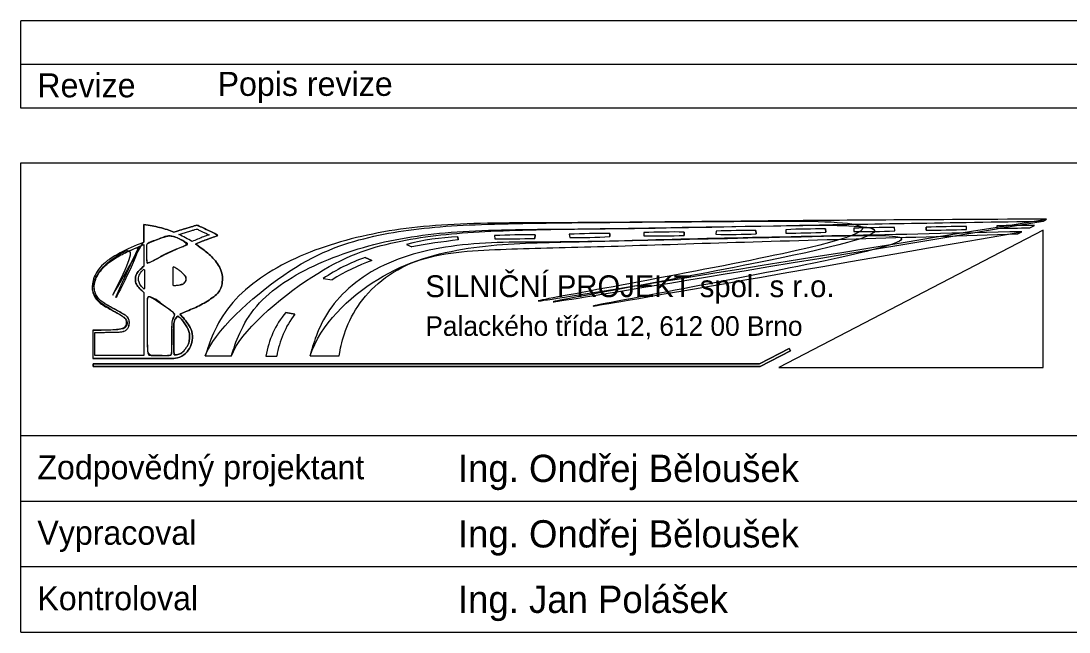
# Model space of a CAD drawing. Extents: x -598463 to -598043, y -1203644 to -1203347.
# Drawn here: x -598223.2 to -598127.3, y -1203502.3 to -1203446.3 of the extents above; entities that cross this region are included whole.
import ezdxf

# ---------------------------------------------------------------- set-up
doc = ezdxf.new("R2010")
doc.units = 0
doc.layers.add('AQP_ROZPISKA', color=7, linetype='Continuous')

msp = doc.modelspace()

# ---------------------------------------------------------------- linework, layer by layer
at = {"layer": 'AQP_ROZPISKA'}
for p, q in [((-598053.212, -1203446.256), (-598223.212, -1203446.256)), ((-598223.212, -1203454.256), (-598223.212, -1203446.256)), ((-598053.212, -1203450.256), (-598223.212, -1203450.256)), ((-598053.212, -1203454.256), (-598223.212, -1203454.256)), ((-598129.633, -1203464.599), (-598129.332, -1203464.413)), ((-598129.633, -1203464.599), (-598129.332, -1203464.413)), ((-598211.962, -1203466.533), (-598211.959, -1203464.908)), ((-598211.959, -1203464.908), (-598211.962, -1203466.533)), ((-598159.57, -1203465.508), (-598159.593, -1203465.806)), ((-598159.57, -1203465.508), (-598159.593, -1203465.806)), ((-598155.933, -1203465.451), (-598155.913, -1203465.767)), ((-598155.913, -1203465.767), (-598155.933, -1203465.451)), ((-598129.655, -1203465.429), (-598153.831, -1203478.006)), ((-598129.655, -1203465.429), (-598153.831, -1203478.006)), ((-598153.186, -1203465.385), (-598153.183, -1203465.7)), ((-598153.186, -1203465.385), (-598153.183, -1203465.7)), ((-598149.577, -1203465.318), (-598149.522, -1203465.625)), ((-598149.522, -1203465.625), (-598149.577, -1203465.318)), ((-598146.97, -1203465.253), (-598146.964, -1203465.544)), ((-598146.97, -1203465.253), (-598146.964, -1203465.544)), ((-598143.228, -1203465.495), (-598143.241, -1203465.178)), ((-598143.228, -1203465.495), (-598143.241, -1203465.178)), ((-598140.34, -1203465.428), (-598140.358, -1203465.169)), ((-598140.358, -1203465.169), (-598140.34, -1203465.428)), ((-598136.674, -1203465.369), (-598136.673, -1203465.099)), ((-598136.674, -1203465.369), (-598136.673, -1203465.099)), ((-598133.888, -1203465.03), (-598133.898, -1203465.262)), ((-598133.888, -1203465.03), (-598133.898, -1203465.262)), ((-598130.866, -1203465.203), (-598130.448, -1203465.011)), ((-598130.866, -1203465.203), (-598130.448, -1203465.011)), ((-598129.655, -1203478.006), (-598129.655, -1203465.429)), ((-598129.655, -1203478.006), (-598129.655, -1203465.429)), ((-598183.211, -1203466.041), (-598183.179, -1203466.326)), ((-598183.179, -1203466.326), (-598183.211, -1203466.041)), ((-598179.853, -1203465.93), (-598179.838, -1203466.21)), ((-598179.853, -1203465.93), (-598179.838, -1203466.21)), ((-598176.149, -1203465.867), (-598176.177, -1203466.19)), ((-598176.177, -1203466.19), (-598176.149, -1203465.867)), ((-598173.029, -1203465.808), (-598172.977, -1203466.094)), ((-598173.029, -1203465.808), (-598172.977, -1203466.094)), ((-598169.299, -1203465.727), (-598169.294, -1203466.016)), ((-598169.294, -1203466.016), (-598169.299, -1203465.727)), ((-598166.189, -1203465.658), (-598166.196, -1203465.937)), ((-598166.189, -1203465.658), (-598166.196, -1203465.937)), ((-598162.495, -1203465.605), (-598162.513, -1203465.913)), ((-598162.513, -1203465.913), (-598162.495, -1203465.605)), ((-598131.972, -1203465.766), (-598131.604, -1203465.567)), ((-598131.972, -1203465.766), (-598131.604, -1203465.567)), ((-598211.963, -1203466.747), (-598211.963, -1203468.727)), ((-598211.963, -1203466.747), (-598211.963, -1203468.727)), ((-598187.929, -1203466.73), (-598187.444, -1203466.945)), ((-598187.929, -1203466.73), (-598187.444, -1203466.945)), ((-598191.699, -1203467.945), (-598191.104, -1203468.212)), ((-598191.104, -1203468.212), (-598191.699, -1203467.945)), ((-598195.545, -1203469.872), (-598194.732, -1203469.978)), ((-598195.545, -1203469.872), (-598194.732, -1203469.978)), ((-598211.963, -1203471.129), (-598211.963, -1203476.903)), ((-598211.963, -1203471.129), (-598211.963, -1203476.903)), ((-598198.975, -1203472.968), (-598198.156, -1203473.126)), ((-598198.156, -1203473.126), (-598198.975, -1203472.968)), ((-598216.635, -1203474.595), (-598216.635, -1203477.181)), ((-598216.635, -1203474.595), (-598216.635, -1203477.181)), ((-598216.458, -1203476.903), (-598216.458, -1203474.799)), ((-598216.458, -1203476.903), (-598216.458, -1203474.799)), ((-598211.963, -1203476.903), (-598216.458, -1203476.903)), ((-598211.963, -1203476.903), (-598216.458, -1203476.903)), ((-598206.34, -1203476.951), (-598203.942, -1203476.951)), ((-598206.34, -1203476.951), (-598203.942, -1203476.951)), ((-598200.784, -1203476.966), (-598199.796, -1203476.966)), ((-598200.784, -1203476.966), (-598199.796, -1203476.966)), ((-598196.752, -1203476.951), (-598194.095, -1203476.951)), ((-598196.752, -1203476.951), (-598194.095, -1203476.951)), ((-598155.62, -1203477.69), (-598152.888, -1203476.278)), ((-598152.888, -1203476.278), (-598155.62, -1203477.69)), ((-598152.78, -1203476.493), (-598155.549, -1203477.932)), ((-598155.549, -1203477.932), (-598152.78, -1203476.493)), ((-598152.888, -1203476.278), (-598152.78, -1203476.493)), ((-598152.78, -1203476.493), (-598152.888, -1203476.278)), ((-598209.725, -1203477.181), (-598216.635, -1203477.181)), ((-598216.635, -1203477.181), (-598210.267, -1203477.181)), ((-598216.607, -1203477.69), (-598155.62, -1203477.69)), ((-598216.607, -1203477.932), (-598216.607, -1203477.69)), ((-598216.607, -1203477.69), (-598216.607, -1203477.932)), ((-598155.62, -1203477.69), (-598216.607, -1203477.69)), ((-598155.549, -1203477.932), (-598216.607, -1203477.932)), ((-598216.607, -1203477.932), (-598155.549, -1203477.932)), ((-598153.831, -1203478.006), (-598129.655, -1203478.006)), ((-598153.831, -1203478.006), (-598129.655, -1203478.006)), ((-598223.212, -1203484.256), (-598053.212, -1203484.256)), ((-598223.212, -1203502.256), (-598223.212, -1203484.256)), ((-598223.212, -1203490.256), (-598053.212, -1203490.256)), ((-598223.212, -1203496.256), (-598053.212, -1203496.256)), ((-598223.212, -1203502.256), (-598053.212, -1203502.256))]:
    msp.add_line(p, q, dxfattribs=at)
msp.add_lwpolyline([(-598223.212, -1203484.256), (-598223.212, -1203459.256), (-598053.212, -1203459.256), (-598053.212, -1203484.256)], dxfattribs=at)
for centre, radius, start, end in [((-598155.311, -1203620.625), 155.175, 90.22938, 91.57245), ((-598155.311, -1203620.625), 155.175, 90.22938, 91.57245), ((-598149.992, -1203540.263), 74.946, 89.68255, 92.44261), ((-598149.992, -1203540.263), 74.946, 89.68255, 92.44261), ((-598142.721, -1203583.61), 118.433, 90.25153, 92.05616), ((-598142.721, -1203583.61), 118.433, 90.25153, 92.05616), ((-598146.074, -1203390.971), 74.579, 269.31629, 272.1867), ((-598146.074, -1203390.971), 74.579, 269.31629, 272.1867), ((-598136.968, -1203546.2), 81.102, 89.79178, 92.39563), ((-598136.968, -1203546.2), 81.102, 89.79178, 92.39563), ((-598141.154, -1203301.248), 164.182, 270.28419, 271.56359), ((-598141.154, -1203301.248), 164.182, 270.28419, 271.56359), ((-598134.121, -1203376.193), 89.069, 270.14354, 272.0944), ((-598134.121, -1203376.193), 89.069, 270.14354, 272.0944), ((-598131.795, -1203533), 68.002, 88.8652, 91.76433), ((-598131.795, -1203533), 68.002, 88.8652, 91.76433), ((-598212.66, -1203474.288), 9.329, 56.87051, 65.23041), ((-598212.66, -1203474.288), 9.329, 56.87051, 65.23041), ((-598182.285, -1203488.869), 22.847, 92.32313, 104.30365), ((-598182.285, -1203488.869), 22.847, 92.32313, 104.30365), ((-598175.607, -1203533.524), 67.623, 96.42923, 100.08156), ((-598175.607, -1203533.524), 67.623, 96.42923, 100.08156), ((-598176.927, -1203529.113), 63.251, 89.29557, 92.65207), ((-598176.927, -1203529.113), 63.251, 89.29557, 92.65207), ((-598178.77, -1203328.379), 137.835, 269.55627, 271.07803), ((-598178.77, -1203328.379), 137.835, 269.55627, 271.07803), ((-598169.502, -1203542.005), 76.278, 89.8478, 92.64998), ((-598169.502, -1203542.005), 76.278, 89.8478, 92.64998), ((-598172.228, -1203414.553), 51.547, 269.16831, 273.26307), ((-598172.228, -1203414.553), 51.547, 269.16831, 273.26307), ((-598164.885, -1203384.363), 81.585, 269.07935, 271.66629), ((-598164.885, -1203384.363), 81.585, 269.07935, 271.66629), ((-598163.514, -1203523.87), 58.274, 88.99776, 92.63098), ((-598163.514, -1203523.87), 58.274, 88.99776, 92.63098), ((-598158.488, -1203397.225), 68.591, 269.07696, 272.15166), ((-598158.488, -1203397.225), 68.591, 269.07696, 272.15166), ((-598154.109, -1203331.069), 134.635, 270.39407, 271.95283), ((-598154.109, -1203331.069), 134.635, 270.39407, 271.95283), ((-598186.881, -1203482.359), 15.199, 108.48338, 124.75427), ((-598186.881, -1203482.359), 15.199, 108.48338, 124.75427), ((-598184.984, -1203485.4), 18.245, 109.60015, 122.29398), ((-598184.984, -1203485.4), 18.245, 109.60015, 122.29398), ((-598192.602, -1203478.26), 8.284, 140.29298, 171.00995), ((-598192.602, -1203478.26), 8.284, 140.29298, 171.00995), ((-598190.881, -1203478.504), 9.047, 143.53116, 170.21409), ((-598190.881, -1203478.504), 9.047, 143.53116, 170.21409)]:
    msp.add_arc(centre, radius, start, end, dxfattribs=at)
for points, degree in [([(-598206.34, -1203476.951), (-598205.581, -1203474.773), (-598198.645, -1203468.365), (-598191.35, -1203465.827), (-598184.203, -1203464.916), (-598174.634, -1203464.75), (-598158.871, -1203464.629), (-598129.332, -1203464.413), (-598206.34, -1203476.951), (-598129.332, -1203464.413)], 3), ([(-598129.332, -1203464.413), (-598139.178, -1203464.47), (-598154.278, -1203464.557), (-598172.572, -1203464.791), (-598183.411, -1203464.704), (-598191.59, -1203465.617), (-598199.259, -1203468.134), (-598204.978, -1203472.435), (-598206.117, -1203476.21), (-598206.34, -1203476.951)], 3), ([(-598211.959, -1203464.908), (-598211.441, -1203464.992), (-598210.507, -1203465.143), (-598209.61, -1203465.452), (-598209.219, -1203465.616)], 3), ([(-598209.219, -1203465.616), (-598209.61, -1203465.452), (-598210.507, -1203465.143), (-598211.441, -1203464.992), (-598211.959, -1203464.908)], 3), ([(-598209.219, -1203465.616), (-598208.634, -1203465.424), (-598207.977, -1203465.213), (-598207.272, -1203465.023), (-598207.114, -1203464.967), (-598206.985, -1203465.009), (-598206.836, -1203465.089), (-598206.278, -1203465.354), (-598205.664, -1203465.621), (-598205.251, -1203465.858), (-598205.17, -1203465.902), (-598205.24, -1203465.955), (-598205.422, -1203466.009), (-598206.117, -1203466.246), (-598206.753, -1203466.497), (-598207.231, -1203466.701)], 3), ([(-598207.231, -1203466.701), (-598206.753, -1203466.497), (-598206.117, -1203466.246), (-598205.422, -1203466.009), (-598205.24, -1203465.955), (-598205.17, -1203465.902), (-598205.251, -1203465.858), (-598205.664, -1203465.621), (-598206.278, -1203465.354), (-598206.836, -1203465.089), (-598206.985, -1203465.009), (-598207.114, -1203464.967), (-598207.272, -1203465.023), (-598207.977, -1203465.213), (-598208.634, -1203465.424), (-598209.219, -1203465.616)], 3), ([(-598208.751, -1203465.817), (-598208.615, -1203465.773), (-598208.35, -1203465.688), (-598207.957, -1203465.567), (-598207.568, -1203465.451), (-598207.285, -1203465.377), (-598207.134, -1203465.33), (-598207.114, -1203465.323)], 3), ([(-598208.751, -1203465.817), (-598208.615, -1203465.773), (-598208.35, -1203465.688), (-598207.957, -1203465.567), (-598207.568, -1203465.451), (-598207.285, -1203465.377), (-598207.134, -1203465.33), (-598207.114, -1203465.323)], 3), ([(-598207.114, -1203465.323), (-598207.089, -1203465.333), (-598207.003, -1203465.383), (-598206.85, -1203465.455), (-598206.595, -1203465.574), (-598206.308, -1203465.704), (-598206.088, -1203465.81), (-598205.993, -1203465.854)], 3), ([(-598207.114, -1203465.323), (-598207.089, -1203465.333), (-598207.003, -1203465.383), (-598206.85, -1203465.455), (-598206.595, -1203465.574), (-598206.308, -1203465.704), (-598206.088, -1203465.81), (-598205.993, -1203465.854)], 3), ([(-598203.942, -1203476.951), (-598203.183, -1203474.773), (-598195.966, -1203468.563), (-598188.945, -1203466.276), (-598181.659, -1203465.471), (-598172.074, -1203465.319), (-598156.079, -1203465.065), (-598129.633, -1203464.599), (-598203.942, -1203476.951), (-598129.633, -1203464.599)], 3), ([(-598203.942, -1203476.951), (-598203.721, -1203476.208), (-598202.586, -1203472.396), (-598196.655, -1203468.43), (-598189.039, -1203466.022), (-598180.895, -1203465.306), (-598169.943, -1203465.363), (-598152.592, -1203464.975), (-598138.447, -1203464.743), (-598129.633, -1203464.599)], 3), ([(-598211.712, -1203466.789), (-598211.708, -1203466.757), (-598211.699, -1203466.691), (-598211.304, -1203466.453), (-598210.636, -1203466.29), (-598209.837, -1203465.882), (-598209.227, -1203465.99), (-598208.802, -1203466.203), (-598208.458, -1203466.353), (-598207.783, -1203466.7), (-598208.166, -1203466.821), (-598208.745, -1203467.067), (-598209.993, -1203467.544), (-598210.829, -1203468.106), (-598211.705, -1203468.529), (-598211.702, -1203468.207), (-598211.723, -1203467.714), (-598211.717, -1203467.193), (-598211.712, -1203466.789)], 3), ([(-598211.712, -1203466.789), (-598211.687, -1203466.7), (-598211.612, -1203466.64), (-598210.58, -1203466.226), (-598209.687, -1203465.947), (-598209.192, -1203466.025), (-598208.85, -1203466.176), (-598208.403, -1203466.386), (-598207.982, -1203466.732), (-598208.191, -1203466.834), (-598208.308, -1203466.881), (-598209.8, -1203467.519), (-598211.517, -1203468.437), (-598211.664, -1203468.477), (-598211.704, -1203468.288), (-598211.712, -1203467.948), (-598211.712, -1203466.789), (-598211.712, -1203466.789), (-598211.712, -1203466.789)], 3), ([(-598205.993, -1203465.854), (-598206.061, -1203465.879), (-598206.263, -1203465.949), (-598206.591, -1203466.076), (-598207.046, -1203466.256), (-598207.368, -1203466.393), (-598207.561, -1203466.475)], 3), ([(-598205.993, -1203465.854), (-598206.061, -1203465.879), (-598206.263, -1203465.949), (-598206.591, -1203466.076), (-598207.046, -1203466.256), (-598207.368, -1203466.393), (-598207.561, -1203466.475)], 3), ([(-598196.752, -1203476.951), (-598195.802, -1203474.094), (-598190.679, -1203469.079), (-598182.256, -1203466.732), (-598173.938, -1203466.523), (-598164.677, -1203466.317), (-598149.021, -1203465.963), (-598131.604, -1203465.567), (-598196.752, -1203476.951), (-598131.604, -1203465.567)], 3), ([(-598131.604, -1203465.567), (-598137.41, -1203465.705), (-598148.434, -1203465.965), (-598162.547, -1203466.225), (-598173.621, -1203466.606), (-598182.407, -1203466.4), (-598190.436, -1203468.176), (-598195.606, -1203472.665), (-598196.491, -1203475.972), (-598196.752, -1203476.951)], 3), ([(-598194.095, -1203476.951), (-598193.963, -1203476.214), (-598193.326, -1203472.678), (-598187.972, -1203467.737), (-598179.884, -1203467.13), (-598171.459, -1203466.998), (-598160.532, -1203466.604), (-598147.065, -1203466.238), (-598136.909, -1203465.921), (-598131.972, -1203465.766)], 3), ([(-598194.095, -1203476.951), (-598193.963, -1203476.214), (-598193.326, -1203472.678), (-598187.972, -1203467.737), (-598179.884, -1203467.13), (-598171.459, -1203466.998), (-598160.532, -1203466.604), (-598147.065, -1203466.238), (-598136.909, -1203465.921), (-598131.972, -1203465.766)], 3), ([(-598212.041, -1203466.559), (-598212.773, -1203466.864), (-598214.203, -1203467.46), (-598216.006, -1203468.662), (-598216.75, -1203470.1), (-598216.684, -1203471.177), (-598216.275, -1203471.956), (-598215.174, -1203472.626), (-598214.27, -1203473.081), (-598213.519, -1203473.556), (-598213.455, -1203473.994), (-598213.673, -1203474.538), (-598214.967, -1203474.589), (-598215.917, -1203474.593), (-598216.635, -1203474.595)], 3), ([(-598216.635, -1203474.595), (-598214.376, -1203474.564), (-598213.667, -1203474.382), (-598213.497, -1203473.999), (-598213.586, -1203473.561), (-598213.846, -1203473.351), (-598215.393, -1203472.481), (-598216.222, -1203471.877), (-598216.672, -1203471.005), (-598216.705, -1203470.527), (-598216.005, -1203468.93), (-598214.206, -1203467.547), (-598212.041, -1203466.559), (-598216.635, -1203474.595), (-598212.041, -1203466.559)], 3), ([(-598216.458, -1203474.799), (-598216.219, -1203474.798), (-598215.826, -1203474.795), (-598215.275, -1203474.789), (-598214.795, -1203474.779), (-598214.379, -1203474.77), (-598214.074, -1203474.754), (-598213.891, -1203474.722), (-598213.752, -1203474.679), (-598213.616, -1203474.609), (-598213.496, -1203474.507), (-598213.404, -1203474.377), (-598213.341, -1203474.235), (-598213.301, -1203474.086), (-598213.284, -1203473.933), (-598213.29, -1203473.777), (-598213.324, -1203473.621), (-598213.392, -1203473.473), (-598213.494, -1203473.351), (-598213.61, -1203473.259), (-598213.823, -1203473.124), (-598214.266, -1203472.866), (-598214.813, -1203472.572), (-598215.282, -1203472.312), (-598215.542, -1203472.159), (-598215.728, -1203472.038), (-598215.9, -1203471.908), (-598216.055, -1203471.764), (-598216.189, -1203471.604), (-598216.303, -1203471.427), (-598216.394, -1203471.238), (-598216.46, -1203471.041), (-598216.498, -1203470.837), (-598216.509, -1203470.63), (-598216.495, -1203470.421), (-598216.457, -1203470.213), (-598216.398, -1203470.008), (-598216.319, -1203469.805), (-598216.221, -1203469.607), (-598216.108, -1203469.414), (-598215.982, -1203469.228), (-598215.843, -1203469.051), (-598215.695, -1203468.882), (-598215.539, -1203468.723), (-598215.374, -1203468.571), (-598215.145, -1203468.38), (-598214.841, -1203468.158), (-598214.457, -1203467.917), (-598214.058, -1203467.696), (-598213.65, -1203467.488), (-598213.235, -1203467.292), (-598212.673, -1203467.043), (-598212.247, -1203466.866), (-598211.963, -1203466.747)], 3), ([(-598216.458, -1203474.799), (-598215.741, -1203474.794), (-598215.28, -1203474.788), (-598214.803, -1203474.779), (-598214.302, -1203474.765), (-598214.032, -1203474.744), (-598213.893, -1203474.719), (-598213.755, -1203474.675), (-598213.621, -1203474.605), (-598213.501, -1203474.502), (-598213.408, -1203474.374), (-598213.344, -1203474.233), (-598213.305, -1203474.085), (-598213.288, -1203473.933), (-598213.294, -1203473.778), (-598213.329, -1203473.624), (-598213.398, -1203473.477), (-598213.501, -1203473.351), (-598213.615, -1203473.258), (-598213.726, -1203473.186), (-598214.138, -1203472.943), (-598214.948, -1203472.496), (-598215.348, -1203472.273), (-598215.543, -1203472.157), (-598215.728, -1203472.035), (-598215.899, -1203471.904), (-598216.052, -1203471.761), (-598216.185, -1203471.601), (-598216.299, -1203471.425), (-598216.39, -1203471.236), (-598216.455, -1203471.039), (-598216.493, -1203470.837), (-598216.505, -1203470.63), (-598216.491, -1203470.422), (-598216.454, -1203470.215), (-598216.395, -1203470.01), (-598216.316, -1203469.807), (-598216.219, -1203469.609), (-598216.106, -1203469.416), (-598215.98, -1203469.23), (-598215.842, -1203469.052), (-598215.694, -1203468.883), (-598215.537, -1203468.724), (-598215.373, -1203468.573), (-598215.202, -1203468.43), (-598214.839, -1203468.164), (-598214.455, -1203467.921), (-598214.057, -1203467.698), (-598213.649, -1203467.49), (-598213.234, -1203467.294), (-598212.814, -1203467.107), (-598211.963, -1203466.747), (-598216.099, -1203474.797), (-598212.389, -1203466.925)], 3), ([(-598212.041, -1203466.559), (-598212.015, -1203466.551), (-598211.988, -1203466.542), (-598211.962, -1203466.533)], 2), ([(-598211.962, -1203466.533), (-598211.988, -1203466.542), (-598212.015, -1203466.551), (-598212.041, -1203466.559)], 2), ([(-598207.231, -1203466.701), (-598207.178, -1203466.736), (-598206.584, -1203467.141), (-598205.614, -1203467.917), (-598204.781, -1203469.104), (-598204.715, -1203470.231), (-598205.047, -1203471.244), (-598206.323, -1203472.045), (-598207.486, -1203472.675), (-598208.426, -1203472.982), (-598208.681, -1203473.152)], 3), ([(-598208.681, -1203473.152), (-598208.426, -1203472.982), (-598207.486, -1203472.675), (-598206.323, -1203472.045), (-598205.047, -1203471.244), (-598204.715, -1203470.231), (-598204.781, -1203469.104), (-598205.614, -1203467.917), (-598206.584, -1203467.141), (-598207.178, -1203466.736), (-598207.231, -1203466.701)], 3), ([(-598211.963, -1203471.129), (-598212.072, -1203471.035), (-598212.344, -1203470.799), (-598212.687, -1203470.39), (-598212.76, -1203469.93), (-598212.714, -1203469.507), (-598212.403, -1203469.118), (-598212.126, -1203468.87), (-598211.963, -1203468.727)], 3), ([(-598211.963, -1203468.727), (-598212.126, -1203468.87), (-598212.403, -1203469.118), (-598212.714, -1203469.507), (-598212.76, -1203469.93), (-598212.687, -1203470.39), (-598212.344, -1203470.799), (-598212.072, -1203471.035), (-598211.963, -1203471.129)], 3), ([(-598211.938, -1203470.83), (-598212.334, -1203470.465), (-598212.487, -1203469.993), (-598212.441, -1203469.582), (-598212.076, -1203469.079), (-598211.908, -1203468.958), (-598211.908, -1203469.14), (-598211.908, -1203469.917), (-598211.908, -1203470.45), (-598211.893, -1203470.709), (-598211.923, -1203470.846), (-598211.938, -1203470.83), (-598211.923, -1203470.846)], 3), ([(-598209.321, -1203469.354), (-598209.322, -1203469.257), (-598209.324, -1203469.103), (-598209.314, -1203468.935), (-598209.313, -1203468.792), (-598209.175, -1203468.791), (-598209.038, -1203468.903), (-598208.813, -1203469.039), (-598208.545, -1203469.252), (-598208.284, -1203469.478), (-598208.064, -1203469.748), (-598208.076, -1203470.022), (-598208.184, -1203470.217), (-598208.375, -1203470.39), (-598208.67, -1203470.439), (-598208.94, -1203470.484), (-598209.123, -1203470.502), (-598209.224, -1203470.513), (-598209.296, -1203470.495), (-598209.313, -1203470.397), (-598209.323, -1203470.216), (-598209.319, -1203469.851), (-598209.32, -1203469.543), (-598209.321, -1203469.354)], 3), ([(-598209.321, -1203469.354), (-598209.321, -1203469.071), (-598209.314, -1203468.902), (-598209.29, -1203468.804), (-598209.218, -1203468.796), (-598209.065, -1203468.876), (-598208.828, -1203469.037), (-598208.568, -1203469.236), (-598208.266, -1203469.512), (-598208.095, -1203469.773), (-598208.102, -1203470.047), (-598208.185, -1203470.201), (-598208.344, -1203470.342), (-598208.69, -1203470.442), (-598208.979, -1203470.486), (-598209.157, -1203470.506), (-598209.229, -1203470.509), (-598209.286, -1203470.487), (-598209.306, -1203470.429), (-598209.318, -1203470.283), (-598209.321, -1203469.923), (-598209.321, -1203469.354), (-598209.321, -1203469.354), (-598209.321, -1203469.354)], 3), ([(-598211.661, -1203475.037), (-598211.663, -1203474.418), (-598211.666, -1203473.567), (-598211.663, -1203472.441), (-598211.669, -1203471.957), (-598211.657, -1203471.399), (-598210.809, -1203471.755), (-598210.204, -1203472.311), (-598209.486, -1203472.799), (-598209.061, -1203473.12), (-598209.217, -1203473.401), (-598209.417, -1203473.733), (-598209.365, -1203474.883), (-598209.372, -1203475.868), (-598209.423, -1203476.697), (-598209.384, -1203476.901), (-598210.165, -1203476.902), (-598210.74, -1203476.887), (-598211.66, -1203476.925), (-598211.636, -1203476.022), (-598211.65, -1203475.468), (-598211.661, -1203475.037)], 3), ([(-598211.661, -1203475.037), (-598211.664, -1203473.16), (-598211.664, -1203472.46), (-598211.664, -1203471.761), (-598211.604, -1203471.489), (-598211.312, -1203471.549), (-598210.054, -1203472.392), (-598209.225, -1203472.997), (-598209.107, -1203473.126), (-598209.165, -1203473.307), (-598209.361, -1203473.714), (-598209.394, -1203474.29), (-598209.415, -1203476.569), (-598209.417, -1203476.642), (-598209.46, -1203476.895), (-598209.521, -1203476.901), (-598211.361, -1203476.913), (-598211.551, -1203476.894), (-598211.65, -1203476.488), (-598211.661, -1203475.037), (-598211.661, -1203475.037), (-598211.661, -1203475.037)], 3), ([(-598208.681, -1203473.152), (-598208.648, -1203473.179), (-598208.337, -1203473.448), (-598207.921, -1203474.013), (-598207.499, -1203474.693), (-598207.49, -1203475.537), (-598207.756, -1203476.288), (-598208.241, -1203476.9), (-598209.114, -1203477.236), (-598209.65, -1203477.169), (-598210.556, -1203477.184), (-598210.002, -1203477.182), (-598209.725, -1203477.181)], 3), ([(-598210.267, -1203477.181), (-598210.267, -1203477.181), (-598210.255, -1203477.179), (-598209.65, -1203477.169), (-598209.114, -1203477.236), (-598208.241, -1203476.9), (-598207.756, -1203476.288), (-598207.49, -1203475.537), (-598207.499, -1203474.693), (-598207.921, -1203474.013), (-598208.337, -1203473.448), (-598208.648, -1203473.179), (-598208.681, -1203473.152)], 3), ([(-598208.861, -1203473.293), (-598208.87, -1203473.302), (-598209.015, -1203473.441), (-598209.242, -1203473.791), (-598209.218, -1203474.465), (-598209.236, -1203475.057), (-598209.229, -1203475.722), (-598209.24, -1203476.269), (-598209.206, -1203476.687), (-598209.193, -1203476.848)], 3), ([(-598209.193, -1203476.848), (-598209.206, -1203476.687), (-598209.24, -1203476.269), (-598209.229, -1203475.722), (-598209.236, -1203475.057), (-598209.218, -1203474.465), (-598209.242, -1203473.791), (-598209.015, -1203473.441), (-598208.87, -1203473.302), (-598208.861, -1203473.293)], 3), ([(-598209.193, -1203476.848), (-598209.168, -1203476.855), (-598209.095, -1203476.873), (-598208.874, -1203476.828), (-598208.482, -1203476.716), (-598208.148, -1203476.302), (-598207.845, -1203475.854), (-598207.788, -1203475.397), (-598207.765, -1203474.981), (-598207.851, -1203474.618), (-598208.023, -1203474.284), (-598208.259, -1203473.906), (-598208.52, -1203473.572), (-598208.758, -1203473.37), (-598208.846, -1203473.304), (-598208.861, -1203473.293)], 3), ([(-598208.861, -1203473.293), (-598208.846, -1203473.304), (-598208.758, -1203473.37), (-598208.52, -1203473.572), (-598208.259, -1203473.906), (-598208.023, -1203474.284), (-598207.851, -1203474.618), (-598207.765, -1203474.981), (-598207.788, -1203475.397), (-598207.845, -1203475.854), (-598208.148, -1203476.302), (-598208.482, -1203476.716), (-598208.874, -1203476.828), (-598209.095, -1203476.873), (-598209.168, -1203476.855), (-598209.193, -1203476.848)], 3)]:
    msp.add_open_spline(points, degree=degree, dxfattribs=at)

# ---------------------------------------------------------------- texts
for s, height, p in [('Revize', 2.2, (-598221.713, -1203453.256)), ('Popis revize', 2.2, (-598205.212, -1203453.123)), ('SILNIČNÍ PROJEKT spol. s r.o.', 2, (-598186.193, -1203471.567)), ('Palackého třída 12, 612 00 Brno', 1.8, (-598186.193, -1203475.112)), ('Zodpovědný projektant', 2.2, (-598221.712, -1203488.256)), ('Ing. Ondřej Běloušek', 2.5, (-598183.212, -1203488.506)), ('Vypracoval', 2.2, (-598221.712, -1203494.256)), ('Ing. Ondřej Běloušek', 2.5, (-598183.212, -1203494.506)), ('Kontroloval', 2.2, (-598221.712, -1203500.256)), ('Ing. Jan Polášek', 2.5, (-598183.212, -1203500.506))]:
    msp.add_text(s, height=height, rotation=360, dxfattribs=at).set_placement(p)

doc.saveas('drawing.dxf')
